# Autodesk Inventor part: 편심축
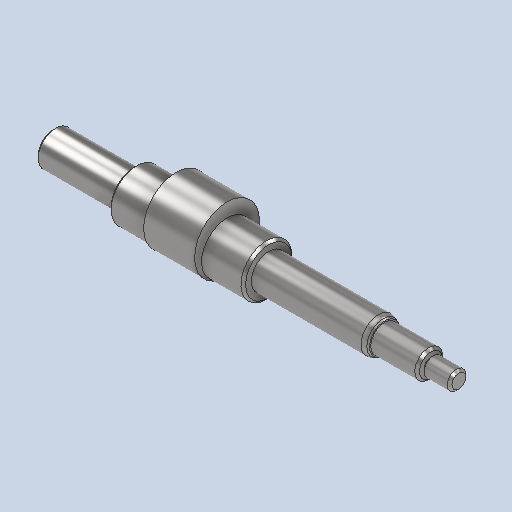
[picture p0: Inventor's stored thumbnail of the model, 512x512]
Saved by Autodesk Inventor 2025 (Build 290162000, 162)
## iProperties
Created: 2024-07
Part Number: 편심축
Material: 강철, 연강
Document SubType Name: Modeling
Designer: Administrator
Density: 7.86 g/cm^3
Appearance: 기본값
Author: jhkim
Sending System: Autodesk Inventor 2025
Preprocessor: ST-DEVELOPER v20
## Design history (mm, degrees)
feature "솔리드1"
node "솔리드2"
